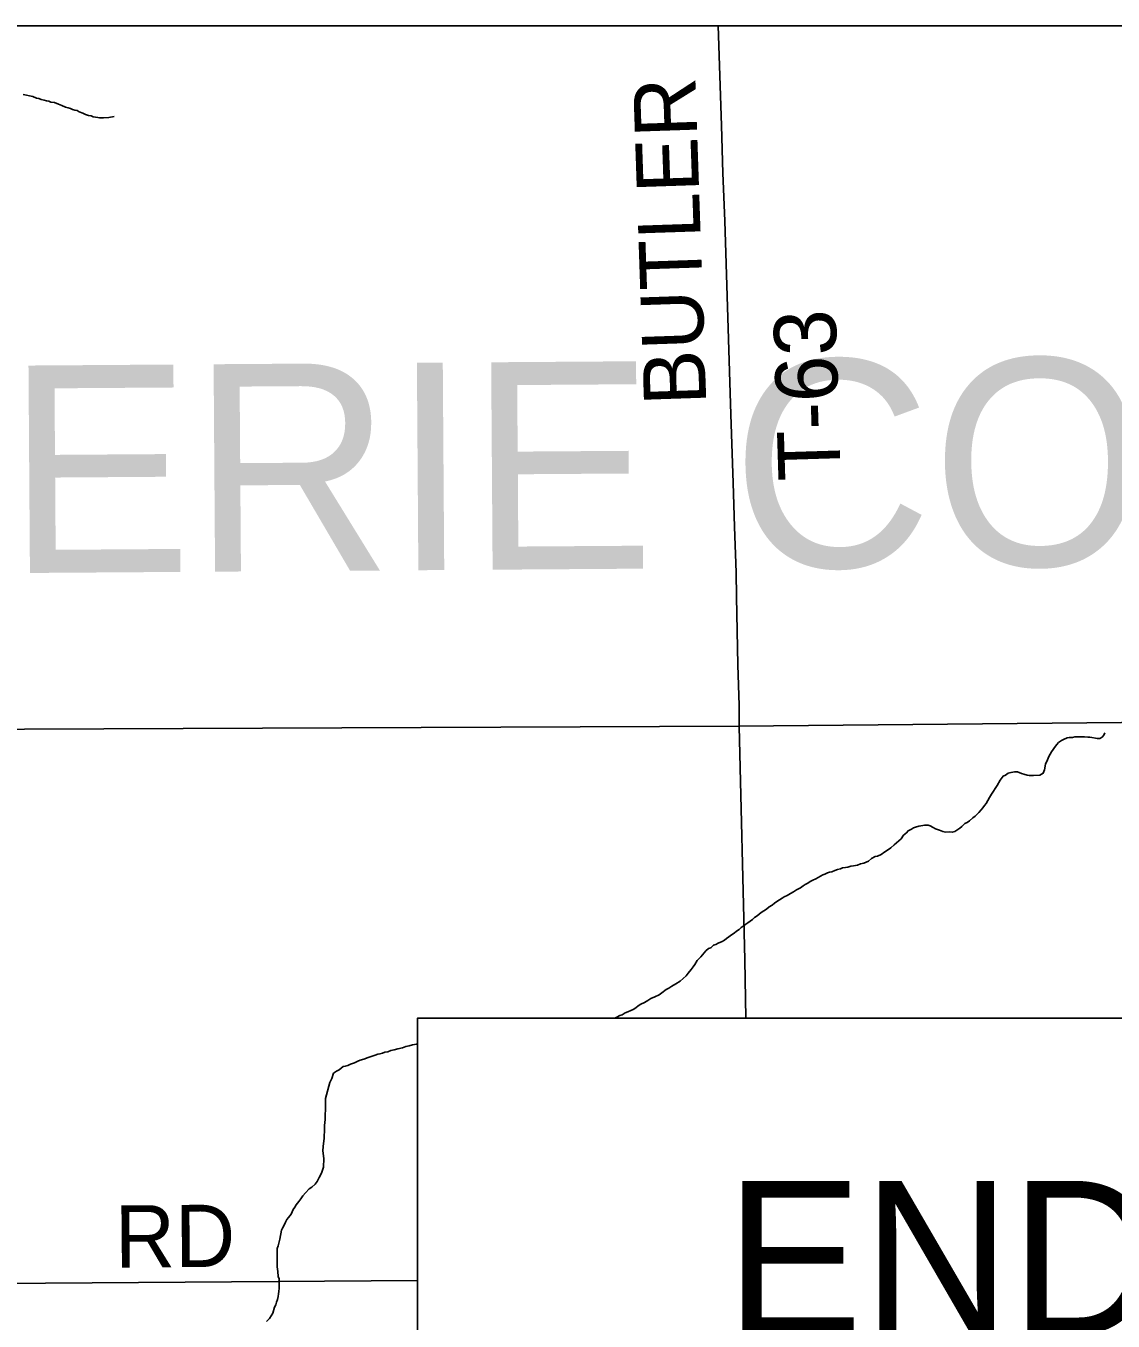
# Model space of a CAD drawing. Extents: x 0 to 34, y 0 to 22.
# Drawn here: x 6.203 to 7.195, y 19.717 to 20.9 of the extents above; entities that cross this region are included whole.
import ezdxf

# ---------------------------------------------------------------- set-up
doc = ezdxf.new("R2010")
doc.units = 0
for name, color, linetype in [('GM_X_Corporation', 7, 'Continuous'), ('GM_X_County_Road', 7, 'Continuous'), ('GM_X_County_Text', 7, 'Continuous'), ('GM_X_Minor_River', 7, 'Continuous'), ('GM_X_Township_Road', 7, 'Continuous'), ('GM_X_Township_Road_Text', 7, 'Continuous'), ('SH_Data', 7, 'Continuous'), ('SH_Text', 7, 'Continuous')]:
    doc.layers.add(name, color=color, linetype=linetype)

msp = doc.modelspace()

# ---------------------------------------------------------------- linework, layer by layer
at = {"layer": 'GM_X_Corporation'}
for points in [[(5.9115, 20.2566), (6.8535, 20.2607), (7.9013, 20.2705), (7.9008, 20.2877), (7.8945, 20.502), (7.8919, 20.5951), (7.8896, 20.6817), (7.8881, 20.7393), (7.8881, 20.7568), (7.8862, 20.7899), (7.8865, 20.8322), (7.8855, 20.8777), (7.8853, 20.9), (2.1, 20.9)], [(5.9115, 20.2566), (6.8535, 20.2607), (7.9013, 20.2705), (7.9008, 20.2877), (7.8945, 20.502), (7.8919, 20.5951), (7.8896, 20.6817), (7.8881, 20.7393), (7.8881, 20.7568), (7.8862, 20.7899), (7.8865, 20.8322), (7.8855, 20.8777), (7.8853, 20.9), (2.6713, 20.9)], [(6.5603, 19.2769), (6.5603, 19.994), (7.9044, 19.994), (7.9013, 20.2705), (6.8535, 20.2607), (5.9115, 20.2566)], [(6.5603, 19.2769), (6.5603, 19.994), (7.9044, 19.994), (7.9013, 20.2705), (6.8535, 20.2607), (5.9115, 20.2566)]]:
    msp.add_lwpolyline(points, dxfattribs=at)
at = {"layer": 'GM_X_County_Road'}
msp.add_lwpolyline([(6.8598, 19.994), (6.8588, 20.0473), (6.8537, 20.2602)], dxfattribs=at)
at = {"layer": 'GM_X_Minor_River'}
for points in [[(6.2833, 20.8172), (6.2787, 20.8164), (6.2737, 20.8159), (6.2703, 20.8159), (6.2684, 20.8163), (6.2665, 20.8166), (6.2642, 20.817), (6.2623, 20.8177), (6.26, 20.8181), (6.2573, 20.8192), (6.2547, 20.8203), (6.2516, 20.8214), (6.2497, 20.8226), (6.2474, 20.8229), (6.2455, 20.8237), (6.2436, 20.8244), (6.2413, 20.8252), (6.239, 20.8259), (6.2356, 20.8274), (6.2325, 20.8285), (6.2291, 20.83), (6.2256, 20.8303), (6.2237, 20.8311), (6.2218, 20.8314), (6.2195, 20.8322), (6.2169, 20.8329), (6.2146, 20.8337), (6.2127, 20.834), (6.2092, 20.8355), (6.2005, 20.8374)], [(7.1875, 20.2546), (7.1864, 20.2523), (7.1848, 20.2504), (7.1829, 20.2493), (7.1806, 20.2493), (7.1738, 20.2505), (7.1719, 20.2505), (7.1689, 20.2509), (7.1662, 20.2509), (7.1632, 20.2509), (7.1601, 20.2509), (7.1578, 20.2502), (7.1548, 20.2502), (7.1529, 20.2498), (7.1498, 20.2483), (7.1479, 20.2476), (7.1452, 20.2457), (7.1437, 20.2438), (7.1414, 20.2411), (7.1403, 20.2393), (7.1387, 20.237), (7.1364, 20.2328), (7.1349, 20.2298), (7.1333, 20.226), (7.1322, 20.2207), (7.131, 20.2176), (7.128, 20.2157), (7.1223, 20.2154), (7.1204, 20.2154), (7.1185, 20.2154), (7.1166, 20.2158), (7.1135, 20.2166), (7.1112, 20.2174), (7.1078, 20.2189), (7.1052, 20.2189), (7.1017, 20.2182), (7.0991, 20.2178), (7.0968, 20.2159), (7.0945, 20.2148), (7.0918, 20.2114), (7.0891, 20.2064), (7.0872, 20.2038), (7.0857, 20.2011), (7.0841, 20.1985), (7.0822, 20.1954), (7.0791, 20.1901), (7.0776, 20.1882), (7.0761, 20.186), (7.0746, 20.1841), (7.0723, 20.1818), (7.0692, 20.1784), (7.0669, 20.1769), (7.0638, 20.1742), (7.0619, 20.1727), (7.0596, 20.1716), (7.057, 20.169), (7.0551, 20.1675), (7.0505, 20.1644), (7.0482, 20.1637), (7.0452, 20.1641), (7.0421, 20.1637), (7.0394, 20.1645), (7.0364, 20.1656), (7.033, 20.1668), (7.0307, 20.1679), (7.0281, 20.1695), (7.0262, 20.1703), (7.0231, 20.1703), (7.0212, 20.1699), (7.0178, 20.1692), (7.0147, 20.1684), (7.0128, 20.1677), (7.0109, 20.1665), (7.0079, 20.165), (7.0063, 20.1631), (7.0037, 20.1609), (7.0014, 20.1578), (6.9995, 20.1559), (6.9972, 20.154), (6.9952, 20.1522), (6.9922, 20.1495), (6.9891, 20.1472), (6.9865, 20.1457), (6.9834, 20.1435), (6.98, 20.142), (6.9777, 20.1416), (6.9746, 20.1397), (6.9716, 20.1374), (6.9674, 20.1356), (6.9643, 20.1348), (6.9617, 20.1337), (6.9579, 20.133), (6.9556, 20.1326), (6.9529, 20.1318), (6.9506, 20.1315), (6.948, 20.1311), (6.9461, 20.1304), (6.9434, 20.1296), (6.9411, 20.1289), (6.9384, 20.1277), (6.9361, 20.1274)], [(6.9361, 20.1274), (6.9342, 20.1266), (6.932, 20.1255), (6.93, 20.1247), (6.9236, 20.1213), (6.9209, 20.1198), (6.9186, 20.1187), (6.9163, 20.1172), (6.914, 20.1161), (6.9121, 20.1149), (6.9098, 20.113), (6.906, 20.1112), (6.9033, 20.1093), (6.9007, 20.1078), (6.8976, 20.1059), (6.8949, 20.1048), (6.893, 20.1036), (6.8904, 20.1021), (6.8881, 20.1006), (6.8858, 20.0991), (6.8839, 20.0972), (6.8812, 20.0957), (6.8785, 20.0934), (6.8762, 20.0919), (6.8739, 20.0904), (6.872, 20.0889), (6.8701, 20.0874), (6.8678, 20.0859), (6.8659, 20.084), (6.8636, 20.0825), (6.8617, 20.081), (6.8598, 20.0798), (6.8575, 20.0779), (6.8556, 20.0768), (6.8537, 20.0749), (6.8514, 20.0734), (6.8491, 20.0715), (6.8468, 20.07), (6.8442, 20.0681), (6.8423, 20.0666), (6.8403, 20.0651), (6.8381, 20.064), (6.8346, 20.0625), (6.8323, 20.0613), (6.8304, 20.0606), (6.8278, 20.0583), (6.8258, 20.0576), (6.8232, 20.0553), (6.8186, 20.05), (6.8155, 20.0466), (6.8132, 20.0428), (6.8117, 20.0409), (6.8098, 20.0383), (6.8071, 20.0349), (6.8052, 20.0326), (6.7998, 20.0277), (6.796, 20.0254), (6.7922, 20.0232), (6.7895, 20.0213), (6.7872, 20.0201), (6.783, 20.0171), (6.7807, 20.0152), (6.7769, 20.0133), (6.7731, 20.0118), (6.7704, 20.01), (6.7674, 20.0081), (6.764, 20.0066), (6.7617, 20.0051), (6.7594, 20.0035), (6.7571, 20.002), (6.7548, 20.0009), (6.7521, 19.9998), (6.7498, 19.9987), (6.7468, 19.9971), (6.7449, 19.9964), (6.7422, 19.9949), (6.7404, 19.994)], [(6.5603, 19.9705), (6.5594, 19.9703), (6.5556, 19.9696), (6.5526, 19.9688), (6.5495, 19.9681), (6.5465, 19.9669), (6.5423, 19.9658), (6.5389, 19.9651), (6.5358, 19.9643), (6.5332, 19.9632), (6.5305, 19.9628), (6.5282, 19.9621), (6.5259, 19.9613), (6.524, 19.961), (6.5217, 19.9602), (6.5187, 19.9591), (6.5152, 19.958), (6.5111, 19.9565), (6.508, 19.9557), (6.5057, 19.9546), (6.5027, 19.9531), (6.4992, 19.952), (6.4966, 19.9508), (6.4943, 19.9501), (6.4924, 19.9497), (6.4886, 19.9467), (6.4863, 19.9456), (6.4836, 19.9437), (6.482, 19.9388), (6.4801, 19.9353), (6.4763, 19.9205), (6.4762, 19.9164), (6.4762, 19.9103), (6.4758, 19.9061), (6.4758, 19.9015), (6.4754, 19.8958), (6.4754, 19.8928), (6.4749, 19.8844), (6.4741, 19.8768), (6.4737, 19.8727), (6.4748, 19.8658), (6.4744, 19.8578), (6.4725, 19.8525), (6.4706, 19.8484), (6.4687, 19.8449), (6.4667, 19.8423), (6.4637, 19.8396), (6.4614, 19.8381), (6.458, 19.8344), (6.4557, 19.8317), (6.4537, 19.8291), (6.4518, 19.8264), (6.4495, 19.8234), (6.4484, 19.8215), (6.4468, 19.8192), (6.4449, 19.815), (6.4426, 19.812), (6.4411, 19.8101), (6.4399, 19.8078), (6.4384, 19.8048), (6.4369, 19.8021), (6.4361, 19.8003), (6.4345, 19.7923), (6.433, 19.7862), (6.4322, 19.7835), (6.4322, 19.7782), (6.4322, 19.7729), (6.4321, 19.7691), (6.4321, 19.7668)], [(6.4321, 19.7668), (6.4329, 19.7626), (6.4332, 19.7581), (6.434, 19.7558), (6.434, 19.7535), (6.4339, 19.7474), (6.4336, 19.7444), (6.4335, 19.7421), (6.4331, 19.7398), (6.4324, 19.7372), (6.4316, 19.7345), (6.4308, 19.7322), (6.4297, 19.73), (6.4281, 19.7247), (6.4251, 19.7197), (6.4224, 19.7171)]]:
    msp.add_lwpolyline(points, dxfattribs=at)
at = {"layer": 'GM_X_Township_Road'}
for points in [[(6.8537, 20.2602), (6.8538, 20.2794), (6.8526, 20.3166), (6.8513, 20.3787), (6.8509, 20.401), (6.8494, 20.4425), (6.8482, 20.4828), (6.8462, 20.545), (6.8406, 20.7219), (6.8389, 20.7654), (6.8376, 20.8089), (6.8346, 20.9)], [(5.4828, 19.7467), (5.8242, 19.7493), (6.1782, 19.7516), (6.5603, 19.7545)]]:
    msp.add_lwpolyline(points, dxfattribs=at)
at = {"layer": 'SH_Data'}
msp.add_line((2.1, 20.9), (8.9, 20.9), dxfattribs=at)
at = {"layer": 'SH_Text'}
msp.add_lwpolyline([(6.5603, 19.994), (8.7801, 19.994), (8.7801, 19.2769), (6.5603, 19.2769)], close=True, dxfattribs=at)

# ---------------------------------------------------------------- texts
at = {"layer": 'GM_X_County_Text'}
msp.add_text('ERIE COUNTY', height=0.189394, rotation=0.4039, dxfattribs=at).set_placement((6.1858, 20.4003))
at = {"layer": 'GM_X_Township_Road_Text'}
for s, rotation, p in [('BUTLER', 91.9392, (6.8238, 20.5543)), ('T-63', 91.756, (6.9464, 20.4856)), ('RD', 0.4937, (6.2843, 19.7661))]:
    msp.add_text(s, height=0.05682, rotation=rotation, dxfattribs=at).set_placement(p)
at = {"layer": 'SH_Text'}
msp.add_text('END ACQUISTION', height=0.14, dxfattribs=at).set_placement((6.8413, 19.7054))

doc.saveas('drawing.dxf')
